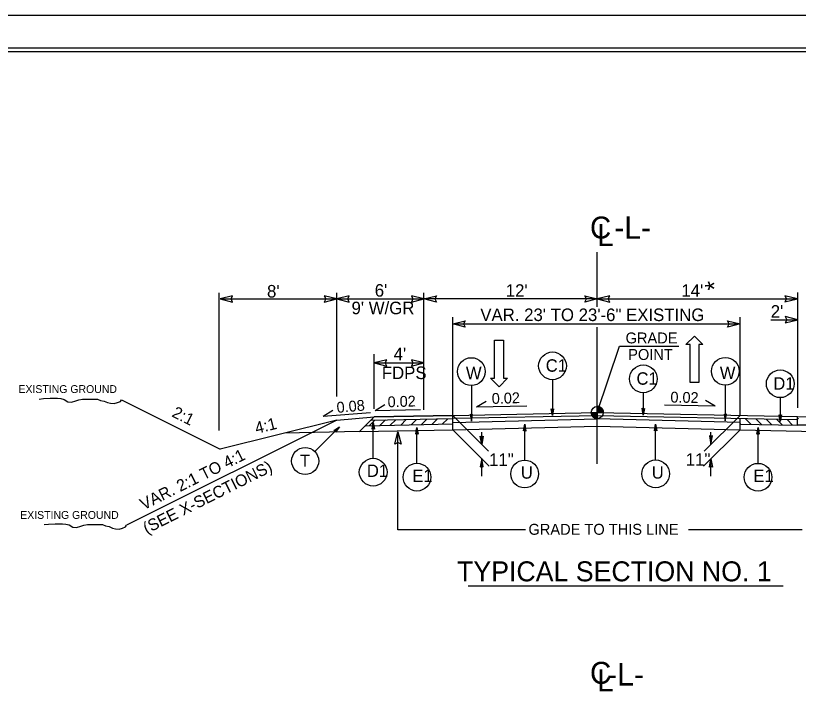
# Model space of a CAD drawing. Extents: x 573786 to 574032, y -53324 to -53148.
# Drawn here: x 573911.1 to 573965.4, y -53261.5 to -53214.4 of the extents above; entities that cross this region are included whole.
import ezdxf

# ---------------------------------------------------------------- set-up
doc = ezdxf.new("R2010")
doc.units = 0
for name, color, linetype in [('Default', 7, 'Continuous'), ('Prop Dimension', 7, 'Continuous'), ('Prop Dimension Text', 7, 'Continuous'), ('Prop Horizontal Alignment Curve and Spiral Data', 7, 'Continuous'), ('Prop Lane Arrow CELL', 7, 'Continuous'), ('Prop Shade Medium', 7, 'Continuous'), ('Sheet Cutting Line CELL', 7, 'Continuous'), ('Sheet Plot Border Inside CELL', 7, 'Continuous'), ('Sheet Plot Border Outside CELL', 7, 'Continuous'), ('Sheet Typical CELL', 7, 'Continuous'), ('Typical Berm Information CELL', 7, 'Continuous'), ('Typical Curb CELL', 7, 'Continuous'), ('Typical Grade Point Symbol CELL', 7, 'Continuous'), ('Typical ID Circle CELL', 7, 'Continuous'), ('Typical Pavement Slope CELL', 7, 'Continuous'), ('Typical Pavement Slope Information CELL', 7, 'Continuous'), ('Typical Shoulder Slope CELL', 7, 'Continuous'), ('Typical Slope Point Local CELL', 7, 'Continuous'), ('Typical Terminator CELL', 7, 'Continuous'), ('Typical Text Centerline CELL', 7, 'Continuous'), ('Typical Text Grade Point CELL', 7, 'Continuous'), ('Typical Text ID Circle CELL', 7, 'Continuous'), ('Typical Text Label CELL', 7, 'Continuous')]:
    doc.layers.add(name, color=color, linetype=linetype)

# ---------------------------------------------------------------- blocks, each defined once
blk = doc.blocks.new('TERMINATOR')
at = {"layer": 'Typical Terminator CELL'}
blk.add_lwpolyline([(-0.469, 0.081), (0, 0), (-0.471, -0.083), (-0.411, 0)], close=True, dxfattribs=at)

msp = doc.modelspace()

# ---------------------------------------------------------------- linework, layer by layer
at = {"layer": 'Default'}
for points in [[(573912.727, -53241.054), (573913.03, -53241.01), (573913.484, -53240.989), (573913.786, -53240.989), (573914.002, -53240.989), (573914.218, -53241.01), (573914.456, -53241.075), (573914.715, -53241.227), (573914.953, -53241.248), (573915.255, -53241.162), (573915.471, -53241.097), (573915.731, -53241.054), (573916.033, -53241.054), (573916.271, -53241.054), (573916.508, -53241.054), (573916.768, -53241.054), (573916.984, -53241.14), (573917.221, -53241.183), (573917.459, -53241.291), (573917.675, -53241.335), (573917.913, -53241.356), (573918.151, -53241.291), (573918.367, -53241.205), (573918.431, -53241.097)], [(573913.072, -53249.754), (573913.375, -53249.711), (573913.828, -53249.689), (573914.131, -53249.689), (573914.347, -53249.689), (573914.563, -53249.711), (573914.801, -53249.776), (573915.06, -53249.927), (573915.298, -53249.949), (573915.6, -53249.862), (573915.816, -53249.797), (573916.075, -53249.754), (573916.378, -53249.754), (573916.616, -53249.754), (573916.853, -53249.754), (573917.112, -53249.754), (573917.329, -53249.841), (573917.566, -53249.884), (573917.804, -53249.992), (573918.02, -53250.035), (573918.258, -53250.057), (573918.495, -53249.992), (573918.711, -53249.905), (573918.776, -53249.797)]]:
    msp.add_lwpolyline(points, dxfattribs=at)
at = {"layer": 'Prop Dimension'}
for p, q in [((573941.406, -53242.177), (573941.406, -53235.355)), ((573961.335, -53242.173), (573961.335, -53235.352)), ((573941.406, -53235.831), (573961.335, -53235.831)), ((573935.634, -53242.885), (573936.012, -53242.507)), ((573936.356, -53242.871), (573936.734, -53242.493)), ((573937.078, -53242.856), (573937.455, -53242.478)), ((573937.799, -53242.842), (573938.177, -53242.464)), ((573938.521, -53242.827), (573938.899, -53242.449)), ((573939.242, -53242.813), (573939.62, -53242.435)), ((573939.964, -53242.798), (573940.342, -53242.42)), ((573940.685, -53242.784), (573941.063, -53242.406)), ((573941.406, -53243.171), (573941.406, -53242.399)), ((573951.438, -53242.468), (573951.438, -53242.198)), ((573961.335, -53243.175), (573961.335, -53242.396)), ((573961.709, -53242.403), (573962.096, -53242.789)), ((573962.431, -53242.417), (573962.818, -53242.804)), ((573963.152, -53242.432), (573963.54, -53242.819)), ((573963.874, -53242.446), (573964.262, -53242.834)), ((573964.595, -53242.461), (573964.984, -53242.849)), ((573965.317, -53242.475), (573965.319, -53242.477)), ((573961.335, -53242.735), (573961.374, -53242.775))]:
    msp.add_line(p, q, dxfattribs=at)
at = {"layer": 'Prop Dimension Text'}
for p, q in [((573925.203, -53243.22), (573925.203, -53233.664)), ((573933.366, -53240.863), (573933.365, -53233.664)), ((573939.406, -53241.787), (573939.406, -53233.664)), ((573965.335, -53241.645), (573965.335, -53233.662)), ((573925.272, -53234.097), (573933.365, -53234.097)), ((573933.365, -53234.097), (573939.406, -53234.096)), ((573951.438, -53234.096), (573939.406, -53234.096)), ((573951.438, -53234.096), (573965.319, -53234.095)), ((573963.482, -53235.54), (573965.335, -53235.54)), ((573935.967, -53241.73), (573935.967, -53237.939)), ((573935.967, -53238.537), (573939.406, -53238.537)), ((573941.406, -53242.669), (573951.438, -53242.418)), ((573961.335, -53242.674), (573951.438, -53242.418)), ((573941.406, -53243.171), (573951.438, -53242.92)), ((573951.438, -53242.92), (573961.335, -53243.175)), ((573937.609, -53250.112), (573937.609, -53243.305)), ((573946.446, -53250.112), (573937.609, -53250.112)), ((573965.642, -53250.111), (573957.762, -53250.111))]:
    msp.add_line(p, q, dxfattribs=at)
at = {"layer": 'Prop Lane Arrow CELL'}
for p, q in [((573957.586, -53237.267), (573958.167, -53236.676)), ((573958.167, -53236.676), (573958.767, -53237.267)), ((573944.309, -53239.593), (573944.309, -53236.968)), ((573944.309, -53236.968), (573944.928, -53236.968)), ((573944.928, -53236.968), (573944.928, -53239.593)), ((573957.867, -53237.267), (573957.586, -53237.267)), ((573957.867, -53239.892), (573957.867, -53237.267)), ((573958.767, -53237.267), (573958.486, -53237.267)), ((573958.486, -53237.267), (573958.486, -53239.892)), ((573944.628, -53240.184), (573944.028, -53239.593)), ((573944.028, -53239.593), (573944.309, -53239.593)), ((573945.209, -53239.593), (573944.628, -53240.184)), ((573944.928, -53239.593), (573945.209, -53239.593)), ((573958.486, -53239.892), (573957.867, -53239.892))]:
    msp.add_line(p, q, dxfattribs=at)
at = {"layer": 'Prop Shade Medium'}
for p, q in [((573941.406, -53242.177), (573951.438, -53241.976)), ((573951.438, -53241.976), (573965.319, -53242.253)), ((573951.438, -53242.198), (573951.438, -53241.976)), ((573935.967, -53242.286), (573935.74, -53242.513)), ((573935.74, -53242.513), (573941.406, -53242.399)), ((573941.406, -53242.177), (573935.967, -53242.286)), ((573941.406, -53242.399), (573941.406, -53242.177)), ((573941.406, -53242.399), (573941.406, -53242.177)), ((573951.438, -53242.198), (573941.406, -53242.399)), ((573965.319, -53242.475), (573951.438, -53242.198))]:
    msp.add_line(p, q, dxfattribs=at)
at = {"layer": 'Sheet Cutting Line CELL'}
msp.add_line((574013.401, -53214.447), (573845.001, -53214.447), dxfattribs=at)
at = {"layer": 'Sheet Plot Border Inside CELL'}
msp.add_lwpolyline([(574012.951, -53216.692), (573846.301, -53216.692), (573846.301, -53322.202), (574012.951, -53322.202)], close=True, dxfattribs=at)
at = {"layer": 'Sheet Plot Border Outside CELL'}
msp.add_lwpolyline([(574013.401, -53214.447), (573845.001, -53214.447), (573845.001, -53324.447), (574013.401, -53324.447)], close=True, dxfattribs=at)
at = {"layer": 'Sheet Typical CELL'}
msp.add_lwpolyline([(574011.701, -53216.947), (573861.701, -53216.947), (573861.701, -53321.947), (574011.701, -53321.947)], close=True, dxfattribs=at)
at = {"layer": 'Typical Curb CELL'}
for p, q in [((573965.319, -53242.856), (573965.319, -53242.253)), ((573965.319, -53242.253), (573967.128, -53242.328)), ((573967.903, -53242.855), (573965.319, -53242.856))]:
    msp.add_line(p, q, dxfattribs=at)
for centre in [(573965.336, -53242.507), (573965.354, -53242.407), (573965.33, -53242.826)]:
    msp.add_circle(centre, 0.00829, dxfattribs=at)
at = {"layer": 'Typical Grade Point Symbol CELL'}
for p, q in [((573951.438, -53241.976), (573952.975, -53237.363)), ((573951.438, -53241.976), (573951.438, -53241.56)), ((573951.022, -53241.976), (573951.438, -53241.976)), ((573951.437, -53242.391), (573951.438, -53241.976)), ((573951.438, -53241.976), (573951.437, -53242.391)), ((573951.853, -53241.976), (573951.438, -53241.976))]:
    msp.add_line(p, q, dxfattribs=at)
for points in [[(573951.441, -53241.56), (573951.441, -53241.56), (573951.442, -53241.976)], [(573951.45, -53241.56), (573951.45, -53241.976)], [(573951.458, -53241.561), (573951.458, -53241.976)], [(573951.466, -53241.561), (573951.466, -53241.976)], [(573951.475, -53241.562), (573951.475, -53241.976)], [(573951.483, -53241.563), (573951.483, -53241.976)], [(573951.491, -53241.564), (573951.491, -53241.976)], [(573951.5, -53241.565), (573951.5, -53241.976)], [(573951.508, -53241.566), (573951.508, -53241.976)], [(573951.516, -53241.567), (573951.516, -53241.976)], [(573951.525, -53241.569), (573951.525, -53241.976)], [(573951.533, -53241.571), (573951.533, -53241.976)], [(573951.541, -53241.573), (573951.541, -53241.976)], [(573951.55, -53241.576), (573951.55, -53241.976)], [(573951.558, -53241.578), (573951.558, -53241.976)], [(573951.566, -53241.58), (573951.566, -53241.976)], [(573951.574, -53241.583), (573951.574, -53241.976)], [(573951.583, -53241.586), (573951.583, -53241.976)], [(573951.591, -53241.59), (573951.591, -53241.976)], [(573951.599, -53241.593), (573951.599, -53241.976)], [(573951.024, -53241.976), (573951.024, -53242.021)], [(573951.032, -53241.976), (573951.032, -53242.07)], [(573951.041, -53241.976), (573951.041, -53242.099)], [(573951.049, -53241.976), (573951.049, -53242.124)], [(573951.057, -53241.976), (573951.057, -53242.144)], [(573951.066, -53241.976), (573951.066, -53242.161)], [(573951.074, -53241.976), (573951.074, -53242.177)], [(573951.082, -53241.976), (573951.082, -53242.192)], [(573951.091, -53241.976), (573951.091, -53242.205)], [(573951.099, -53241.976), (573951.099, -53242.217)], [(573951.107, -53241.976), (573951.107, -53242.228)], [(573951.115, -53241.976), (573951.115, -53242.238)], [(573951.124, -53241.976), (573951.124, -53242.248)], [(573951.132, -53241.976), (573951.132, -53242.257)], [(573951.14, -53241.976), (573951.14, -53242.267)], [(573951.149, -53241.976), (573951.149, -53242.275)], [(573951.157, -53241.976), (573951.157, -53242.282)], [(573951.165, -53241.976), (573951.165, -53242.29)], [(573951.174, -53241.976), (573951.174, -53242.297)], [(573951.182, -53241.976), (573951.182, -53242.304)], [(573951.19, -53241.976), (573951.19, -53242.31)], [(573951.199, -53241.976), (573951.199, -53242.316)], [(573951.207, -53241.976), (573951.207, -53242.321)], [(573951.215, -53241.976), (573951.215, -53242.327)], [(573951.224, -53241.976), (573951.224, -53242.332)], [(573951.232, -53241.976), (573951.232, -53242.337)], [(573951.24, -53241.976), (573951.24, -53242.341)], [(573951.248, -53241.976), (573951.248, -53242.346)], [(573951.257, -53241.976), (573951.257, -53242.35)], [(573951.265, -53241.976), (573951.265, -53242.353)], [(573951.273, -53241.976), (573951.273, -53242.357)], [(573951.282, -53241.976), (573951.282, -53242.361)], [(573951.29, -53241.976), (573951.29, -53242.365)], [(573951.298, -53241.976), (573951.298, -53242.367)], [(573951.307, -53241.976), (573951.307, -53242.37)], [(573951.315, -53241.976), (573951.315, -53242.373)], [(573951.323, -53241.976), (573951.323, -53242.375)], [(573951.332, -53241.976), (573951.332, -53242.377)], [(573951.34, -53241.976), (573951.34, -53242.379)], [(573951.348, -53241.976), (573951.348, -53242.381)], [(573951.357, -53241.976), (573951.357, -53242.383)], [(573951.365, -53241.976), (573951.365, -53242.385)], [(573951.373, -53241.976), (573951.373, -53242.386)], [(573951.381, -53241.976), (573951.381, -53242.388)], [(573951.39, -53241.976), (573951.39, -53242.388)], [(573951.398, -53241.976), (573951.398, -53242.389)], [(573951.406, -53241.976), (573951.406, -53242.39)], [(573951.415, -53241.976), (573951.415, -53242.39)], [(573951.423, -53241.976), (573951.423, -53242.391)], [(573951.431, -53241.976), (573951.431, -53242.391), (573951.431, -53242.391)], [(573951.608, -53241.597), (573951.608, -53241.976)], [(573951.616, -53241.601), (573951.616, -53241.976)], [(573951.624, -53241.604), (573951.624, -53241.976)], [(573951.633, -53241.609), (573951.633, -53241.976)], [(573951.641, -53241.614), (573951.641, -53241.976)], [(573951.649, -53241.618), (573951.649, -53241.976)], [(573951.658, -53241.623), (573951.658, -53241.976)], [(573951.666, -53241.628), (573951.666, -53241.976)], [(573951.674, -53241.634), (573951.674, -53241.976)], [(573951.683, -53241.64), (573951.683, -53241.976)], [(573951.691, -53241.646), (573951.691, -53241.976)], [(573951.699, -53241.652), (573951.699, -53241.976)], [(573951.707, -53241.66), (573951.707, -53241.976)], [(573951.716, -53241.667), (573951.716, -53241.976)], [(573951.724, -53241.675), (573951.724, -53241.976)], [(573951.732, -53241.683), (573951.732, -53241.976)], [(573951.741, -53241.691), (573951.741, -53241.976)], [(573951.749, -53241.7), (573951.749, -53241.976)], [(573951.757, -53241.711), (573951.757, -53241.976)], [(573951.766, -53241.721), (573951.766, -53241.976)], [(573951.774, -53241.732), (573951.774, -53241.976)], [(573951.782, -53241.744), (573951.782, -53241.976)], [(573951.791, -53241.757), (573951.791, -53241.976)], [(573951.799, -53241.771), (573951.799, -53241.976)], [(573951.807, -53241.785), (573951.807, -53241.976)], [(573951.815, -53241.803), (573951.815, -53241.976)], [(573951.824, -53241.822), (573951.824, -53241.976)], [(573951.832, -53241.845), (573951.832, -53241.976)], [(573951.84, -53241.874), (573951.84, -53241.976)], [(573951.849, -53241.917), (573951.849, -53241.976)]]:
    msp.add_lwpolyline(points, dxfattribs=at)
msp.add_circle((573951.437, -53241.976), 0.416, dxfattribs=at)
for start, end in [(359.9928, 89.9928), (179.9928, 269.9928)]:
    msp.add_arc((573951.437, -53241.976), 0.416, start, end, dxfattribs=at)
at = {"layer": 'Typical ID Circle CELL'}
for p, q in [((573948.328, -53239.7), (573948.328, -53242.185)), ((573942.702, -53240.097), (573942.702, -53242.582)), ((573960.312, -53240.075), (573960.312, -53242.56)), ((573954.624, -53240.602), (573954.624, -53242.155)), ((573964.126, -53240.945), (573964.126, -53242.602)), ((573935.889, -53245.153), (573935.889, -53242.667)), ((573943.89, -53244.659), (573941.406, -53242.177)), ((573958.851, -53244.656), (573961.335, -53242.173)), ((573931.832, -53244.678), (573933.546, -53242.965)), ((573938.924, -53245.499), (573938.924, -53243.013)), ((573943.935, -53245.698), (573941.406, -53243.171)), ((573946.401, -53245.275), (573946.401, -53242.789)), ((573955.481, -53245.27), (573955.481, -53242.784)), ((573958.806, -53245.703), (573961.335, -53243.175)), ((573962.584, -53245.501), (573962.584, -53243.016)), ((573943.42, -53244.19), (573943.42, -53243.341)), ((573959.321, -53244.187), (573959.321, -53243.338)), ((573943.42, -53246.393), (573943.42, -53245.266)), ((573959.321, -53246.39), (573959.321, -53245.188))]:
    msp.add_line(p, q, dxfattribs=at)
for centre, radius in [((573948.328, -53238.739), 0.962), ((573942.702, -53239.135), 0.962), ((573960.312, -53239.114), 0.962), ((573954.624, -53239.641), 0.962), ((573964.126, -53239.983), 0.962), ((573931.17, -53245.342), 0.938), ((573935.889, -53246.114), 0.962), ((573946.401, -53246.236), 0.962), ((573955.481, -53246.231), 0.962), ((573938.924, -53246.46), 0.962), ((573962.584, -53246.463), 0.962)]:
    msp.add_circle(centre, radius, dxfattribs=at)
at = {"layer": 'Typical Pavement Slope CELL'}
for p, q in [((573935.74, -53242.513), (573941.406, -53242.399)), ((573935.967, -53242.286), (573941.406, -53242.177)), ((573941.406, -53242.177), (573941.406, -53242.177)), ((573934.953, -53243.3), (573941.406, -53243.171)), ((573935.362, -53242.89), (573941.406, -53242.769))]:
    msp.add_line(p, q, dxfattribs=at)
at = {"layer": 'Typical Pavement Slope Information CELL'}
for p, q in [((573936.034, -53241.834), (573936.707, -53241.427)), ((573943.049, -53241.591), (573943.722, -53241.184)), ((573943.049, -53241.591), (573946.54, -53241.521)), ((573959.623, -53241.543), (573956.107, -53241.473)), ((573959.623, -53241.543), (573958.95, -53241.137)), ((573932.427, -53242.222), (573933.1, -53241.815)), ((573932.427, -53242.222), (573935.701, -53241.976)), ((573936.034, -53241.834), (573939.178, -53241.771))]:
    msp.add_line(p, q, dxfattribs=at)
at = {"layer": 'Typical Shoulder Slope CELL'}
msp.add_line((573933.366, -53242.503), (573935.967, -53242.286), dxfattribs=at)
at = {"layer": 'Typical Slope Point Local CELL'}
for p, q in [((573918.431, -53241.097), (573925.279, -53244.52)), ((573933.366, -53242.503), (573918.776, -53249.797)), ((573933.366, -53242.503), (573925.273, -53244.526)), ((573934.951, -53243.302), (573935.967, -53242.286)), ((573961.335, -53242.774), (573965.319, -53242.857)), ((573961.335, -53243.175), (573969.184, -53243.338)), ((573965.319, -53242.857), (573965.319, -53242.856)), ((573934.951, -53243.302), (573929.747, -53243.407))]:
    msp.add_line(p, q, dxfattribs=at)
at = {"layer": 'Typical Terminator CELL'}
for points in [[(573942.621, -53242.113), (573942.702, -53242.582), (573942.785, -53242.111), (573942.702, -53242.171)], [(573948.409, -53241.717), (573948.328, -53242.185), (573948.245, -53241.714), (573948.328, -53241.774)], [(573954.705, -53241.686), (573954.624, -53242.155), (573954.541, -53241.684), (573954.624, -53241.744)], [(573960.232, -53242.092), (573960.312, -53242.56), (573960.396, -53242.089), (573960.312, -53242.149)], [(573964.207, -53242.133), (573964.126, -53242.602), (573964.043, -53242.131), (573964.126, -53242.191)], [(573935.809, -53243.136), (573935.889, -53242.667), (573935.973, -53243.138), (573935.889, -53243.078)], [(573933.167, -53243.232), (573933.546, -53242.965), (573933.279, -53243.347), (573933.263, -53243.248)], [(573938.843, -53243.482), (573938.924, -53243.013), (573939.007, -53243.485), (573938.924, -53243.425)], [(573946.321, -53243.258), (573946.401, -53242.789), (573946.485, -53243.26), (573946.401, -53243.201)], [(573955.401, -53243.253), (573955.481, -53242.784), (573955.565, -53243.256), (573955.481, -53243.196)], [(573962.504, -53243.485), (573962.584, -53243.016), (573962.668, -53243.487), (573962.584, -53243.427)], [(573943.524, -53243.609), (573943.423, -53244.194), (573943.319, -53243.605), (573943.423, -53243.68)], [(573959.222, -53243.598), (573959.323, -53244.184), (573959.427, -53243.595), (573959.323, -53243.67)], [(573943.526, -53245.748), (573943.425, -53245.163), (573943.321, -53245.752), (573943.425, -53245.677)], [(573959.22, -53245.774), (573959.321, -53245.188), (573959.425, -53245.778), (573959.321, -53245.703)]]:
    msp.add_lwpolyline(points, close=True, dxfattribs=at)
at = {"layer": 'Typical Text Centerline CELL'}
for p, q in [((573951.437, -53232.15), (573951.437, -53230.846)), ((573951.437, -53234.637), (573951.437, -53232.15)), ((573951.438, -53236.946), (573951.438, -53236.063)), ((573951.438, -53245.545), (573951.438, -53236.946))]:
    msp.add_line(p, q, dxfattribs=at)
at = {"layer": 'Typical Text Grade Point CELL'}
msp.add_line((573952.975, -53237.363), (573957.081, -53237.363), dxfattribs=at)
at = {"layer": 'Typical Text Label CELL'}
msp.add_line((573942.487, -53254.004), (573964.334, -53254.003), dxfattribs=at)

# ---------------------------------------------------------------- block references
at = {"layer": 'Prop Dimension Text'}
for p, xscale, yscale, rotation in [((573925.272, -53234.097), 1.8461659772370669, -2.649824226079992, -179.99768562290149), ((573933.365, -53234.097), 1.8461659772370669, -2.649824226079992, 0.002314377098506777), ((573933.365, -53234.097), 1.8461659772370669, -2.649824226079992, -179.99768562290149), ((573939.406, -53234.096), 1.8461659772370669, -2.649824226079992, 0.002314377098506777), ((573939.406, -53234.096), 1.846165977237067, 2.6498242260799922, -179.99768562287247), ((573951.438, -53234.096), 1.846165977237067, 2.6498242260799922, 0.0023143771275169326), ((573951.438, -53234.096), 1.8461659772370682, -2.6498242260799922, -179.9976856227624), ((573965.319, -53234.095), 1.8461659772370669, -2.649824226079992, 0.002314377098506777), ((573941.406, -53235.831), 1.846165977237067, 2.6498242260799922, -179.99768562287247), ((573961.335, -53235.831), 1.846165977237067, 2.6498242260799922, 0.0023143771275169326), ((573965.335, -53235.54), 1.8461659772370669, -2.649824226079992, 0.002314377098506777), ((573935.967, -53238.537), 1.8461659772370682, -2.6498242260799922, -179.9976856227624), ((573939.406, -53238.537), 1.8461659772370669, -2.649824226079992, 0.002314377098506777), ((573937.609, -53243.305), 1.846165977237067, 2.6498242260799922, 90.0023143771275)]:
    msp.add_blockref('TERMINATOR', p, dxfattribs=dict(at, xscale=xscale, yscale=yscale, rotation=rotation))

# ---------------------------------------------------------------- texts
for s, height, rotation, p in [('*', 1.28, 90, (573960.194, -53233.515)), ("8'", 0.8705, 0.0023, (573928.525, -53234)), ("6'", 0.8705, 0.0023, (573935.999, -53233.939)), ("12'", 0.8705, 0.0023, (573945.086, -53233.951)), ("14'", 0.8705, 0.0023, (573957.265, -53233.95)), ("9' W/GR", 0.8705, 0.0023, (573934.388, -53235.158)), ("2'", 0.8705, 0.0023, (573963.467, -53235.399)), ('VAR. 23\' TO 23\'-6" EXISTING', 0.87047, 0.0023, (573943.321, -53235.632)), ("4'", 0.8705, 0.0023, (573937.307, -53238.35)), ('FDPS', 0.8705, 0.0023, (573936.488, -53239.656)), ('11"', 0.8705, 359.9977, (573943.929, -53245.679)), ('11"', 0.8705, 0.0023, (573957.571, -53245.669))]:
    msp.add_text(s, height=height, rotation=rotation, dxfattribs=at).set_placement(p)
at = {"layer": 'Prop Horizontal Alignment Curve and Spiral Data'}
for p in [(573952.606, -53229.928), (573952.112, -53260.914)]:
    msp.add_text('-L-', height=1.5672, rotation=0.0023, dxfattribs=at).set_placement(p)
at = {"layer": 'Typical Berm Information CELL'}
for s, rotation, p in [('0.02', 1.8107, (573936.902, -53241.614)), ('0.02', 1.8107, (573944.127, -53241.382)), ('0.08', 5.0828, (573933.387, -53242.005))]:
    msp.add_text(s, height=0.75, rotation=rotation, dxfattribs=at).set_placement(p)
at = {"layer": 'Typical Pavement Slope Information CELL'}
msp.add_text('0.02', height=0.75, rotation=358.8566, dxfattribs=at).set_placement((573956.503, -53241.28))
at = {"layer": 'Typical Slope Point Local CELL'}
for s, height, rotation, p in [('EXISTING GROUND', 0.54395, 0.0023, (573911.285, -53240.621)), ('2:1', 0.8124, 333.4373, (573921.866, -53242.235)), ('4:1', 0.8124, 14.0386, (573927.799, -53243.461)), ('VAR. 2:1 TO 4:1', 0.81244, 26.5645, (573919.965, -53248.759)), ('(SEE X-SECTIONS)', 0.81244, 26.5645, (573920.177, -53250.414)), ('EXISTING GROUND', 0.54395, 0.0023, (573911.407, -53249.354))]:
    msp.add_text(s, height=height, rotation=rotation, dxfattribs=at).set_placement(p)
at = {"layer": 'Typical Text Centerline CELL'}
for s, height, rotation, p in [('C', 1.523, 0.0023, (573950.93, -53229.907)), ('L', 1.524, 359.9492, (573951.437, -53230.427)), ('C', 1.523, 0.0023, (573950.93, -53260.796)), ('L', 1.524, 359.9492, (573951.437, -53261.316))]:
    msp.add_text(s, height=height, rotation=rotation, dxfattribs=at).set_placement(p)
at = {"layer": 'Typical Text Grade Point CELL'}
for s, height, p in [('GRADE', 0.7573, (573953.398, -53237.182)), ('POINT', 0.7573, (573953.58, -53238.329)), ('GRADE TO THIS LINE', 0.75728, (573946.661, -53250.457))]:
    msp.add_text(s, height=height, rotation=0.0023, dxfattribs=at).set_placement(p)
at = {"layer": 'Typical Text ID Circle CELL'}
for s, height, p in [('C1', 0.8608, (573947.859, -53239.145)), ('C1', 0.8608, (573954.155, -53240.047)), ('D1', 0.8608, (573963.645, -53240.389)), ('T ', 0.8393, (573930.821, -53245.728)), ('D1', 0.8608, (573935.452, -53246.444)), ('E1', 0.8608, (573938.604, -53246.79)), ('U', 0.861, (573946.132, -53246.566)), ('U', 0.861, (573955.212, -53246.561)), ('E1', 0.8608, (573962.264, -53246.793))]:
    msp.add_text(s, height=height, rotation=360, dxfattribs=at).set_placement(p)
for p in [(573942.323, -53239.666), (573959.934, -53239.645)]:
    msp.add_text('W', height=0.861, dxfattribs=at).set_placement(p)
at = {"layer": 'Typical Text Label CELL'}
msp.add_text(' TYPICAL SECTION NO. 1', height=1.38527, rotation=0.0023, dxfattribs=at).set_placement((573941.194, -53253.686))

doc.saveas('drawing.dxf')
